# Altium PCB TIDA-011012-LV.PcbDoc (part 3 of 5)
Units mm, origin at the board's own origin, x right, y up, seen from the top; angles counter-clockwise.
Board outline 250 x 280 mm, 4 copper layers (Top Layer, Layer 1, Layer 2, Bottom Layer), stack 2.208 mm thick; 410 components, 230 nets, 1280 pads, 1868 vias.
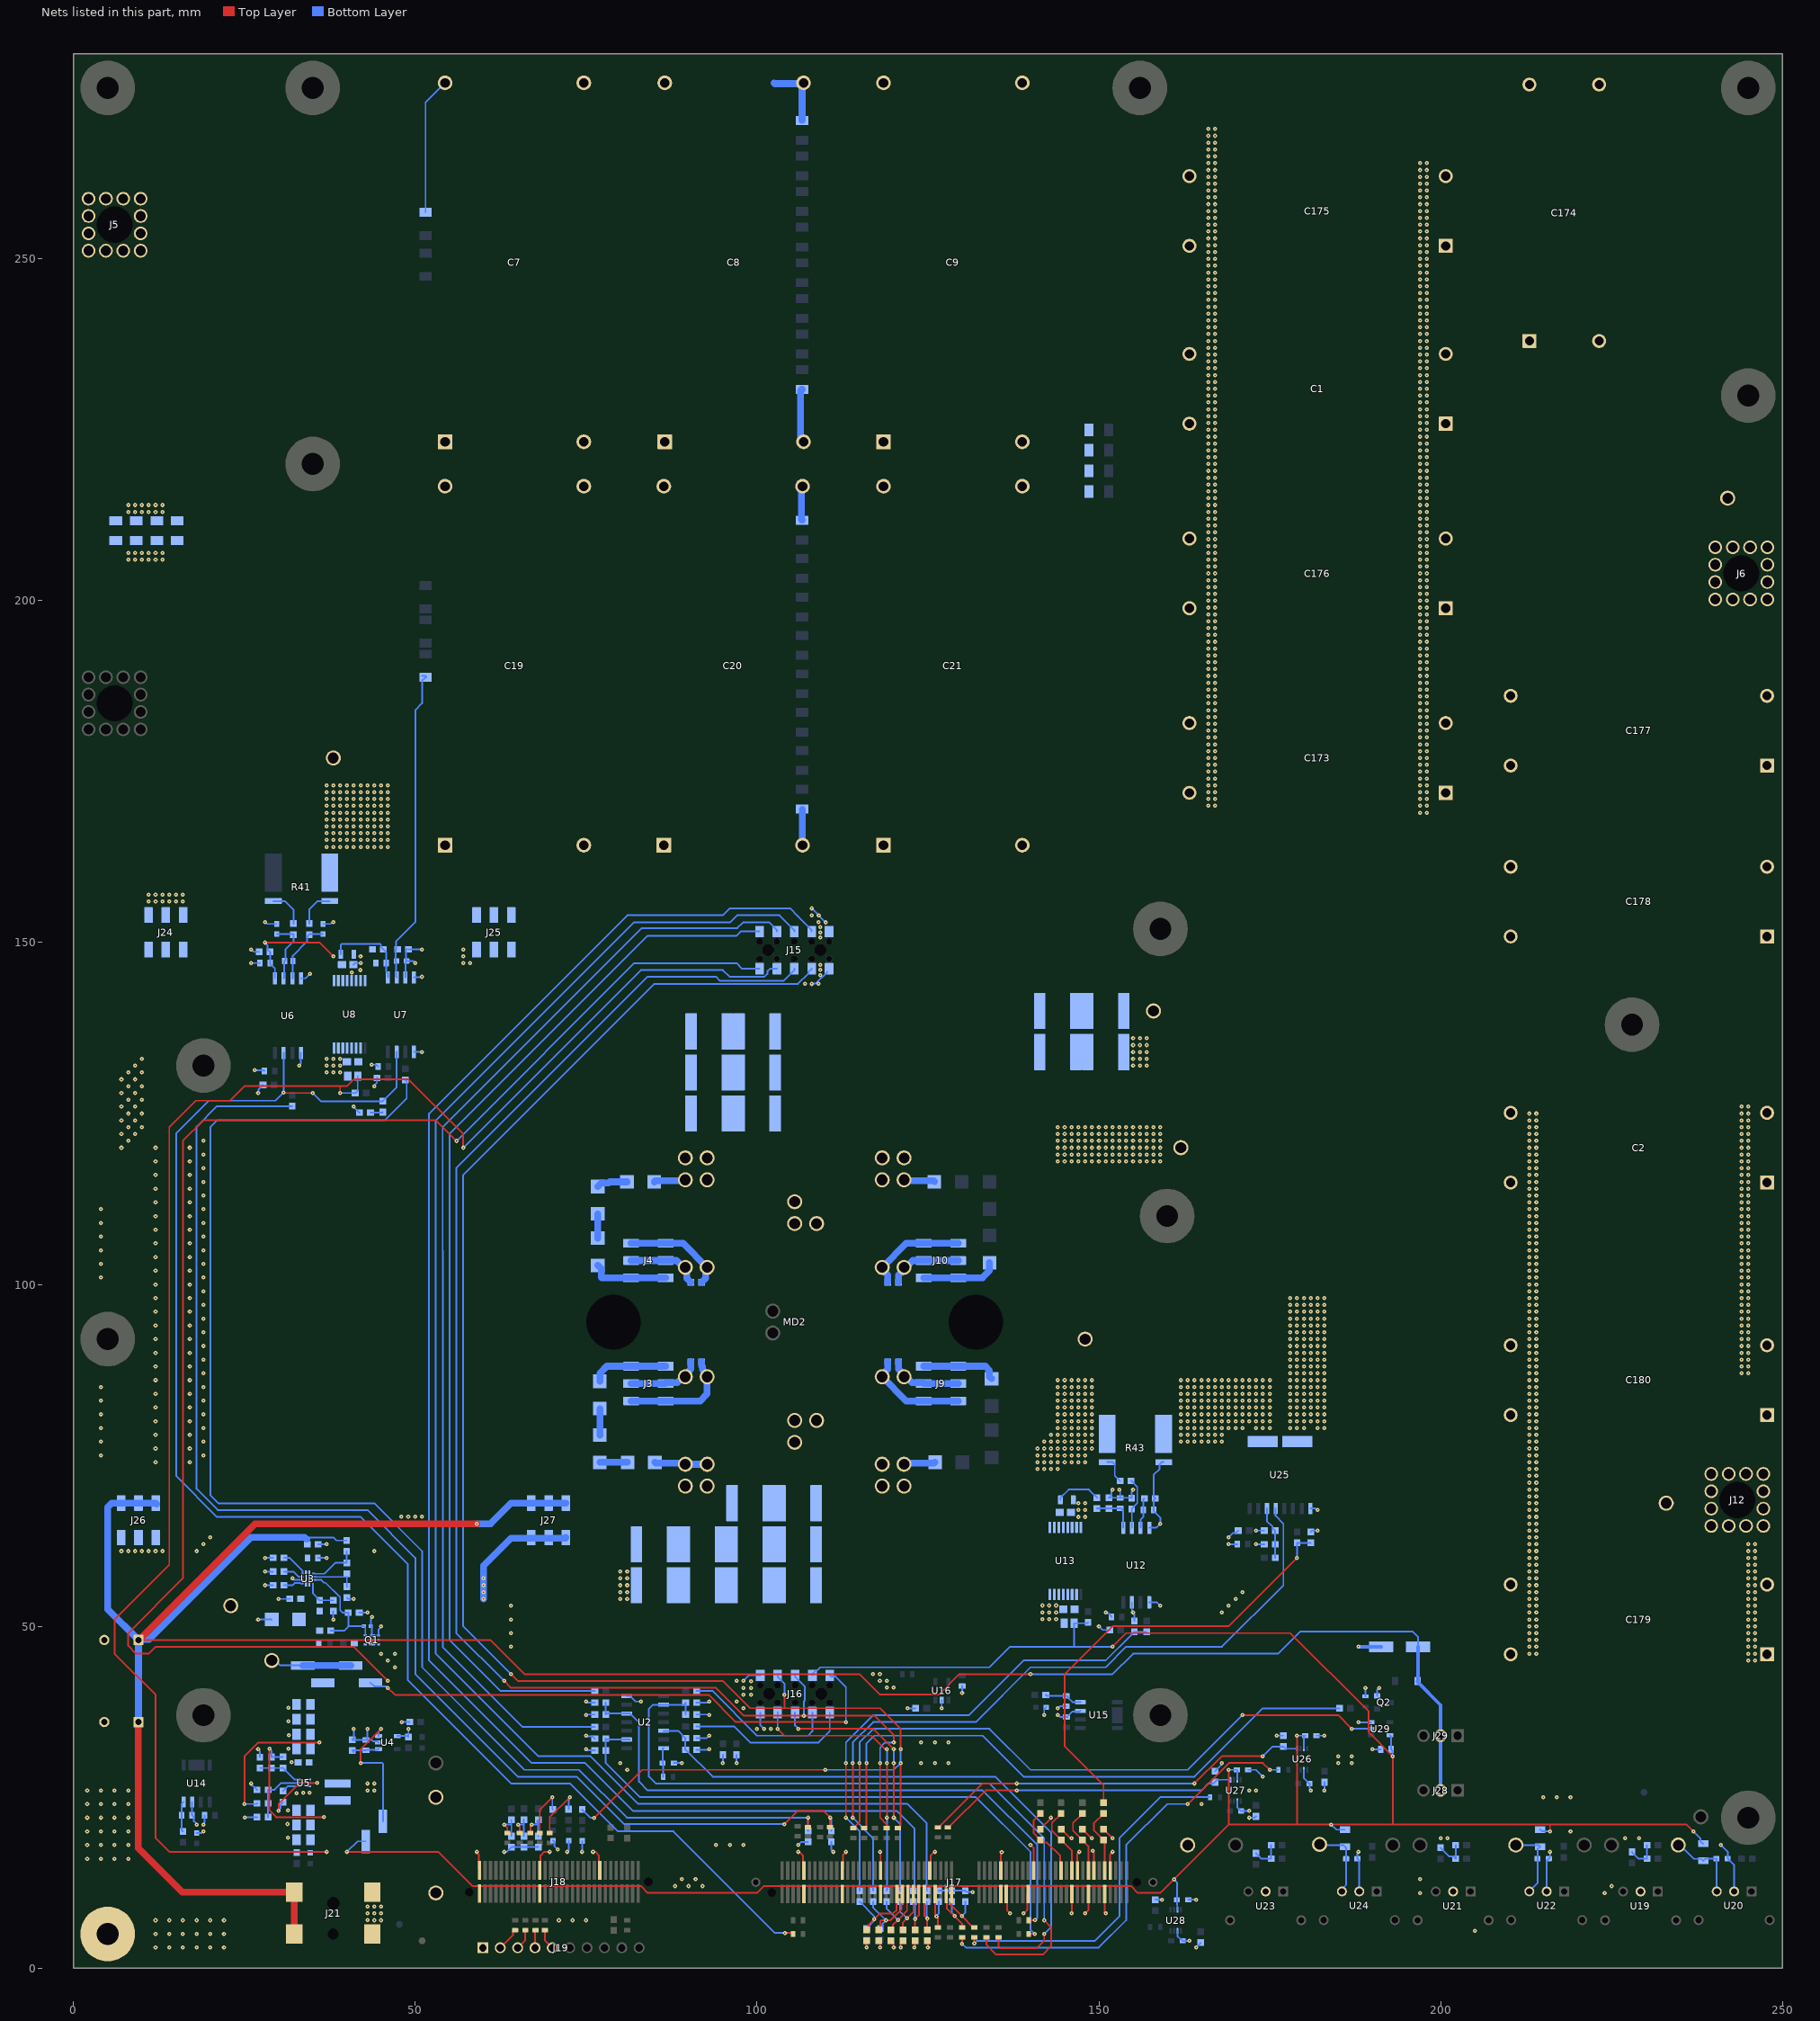
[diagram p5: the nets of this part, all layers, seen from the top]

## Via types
v1: diameter 0.6, hole 0.2, Top Layer to Bottom Layer, tented both sides, 1862 vias
v2: diameter 0.61, hole 0.203, Top Layer to Bottom Layer, tented both sides, 6 vias

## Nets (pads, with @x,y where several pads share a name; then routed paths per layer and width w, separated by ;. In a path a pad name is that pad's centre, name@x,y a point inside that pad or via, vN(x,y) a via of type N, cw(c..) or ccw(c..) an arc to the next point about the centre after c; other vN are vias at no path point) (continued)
5V: C63.1 C67.1 C68.1 C69.1 C88.2 C90.1 C119.2 C121.1 C137.2 C142.2 C144.2 C146.1 D31.2 J15.3 J16.3 J17.48 J17.84 J17.98 J17.112 J18.158 J18.180 J23.1 L1.1 L2.1 L3.1 L7.2 R144.2 R165.2 R185.2 U8.2 U8.3 U13.2 U13.3 U26.7 U27.7 U28.7 U29.5 | length 640.3
  Top Layer w0.25: v1(28.65,32.087) 28.65,23.087 29.65,22.087 v1(36.65,22.087) ; v1(37,17) 14,17 12,19 12,40 6,46 6,51 14,59 14,123 17.875,126.875 22.875,126.875 25,129 39,129 40,129 41,130 ; v1(40,17) 53.362,17 58.362,12 J18.180@59.399,12 ; J18.180@59.399,10.906 J18.180@59.399,12 ; J18.158@68.199,10.906 J18.158@68.199,12 ; J17.112@106.867,10.862 J17.112@106.867,12 ; J17.98@112.467,10.862 J17.98@112.467,12 ; J17.84@118.067,10.862 J17.84@118.067,12 ; J17.48@135.667,10.862 J17.48@135.667,12 ; v1(152,47) 154,49 178,49 189.467,37.533 189.467,34.533 v1(193,31) 193,21 ; v1(169,29) 169,21 ; v1(179,34) 179,21.077 178.923,21 ; v1(216,20) 216,20.96 215.96,21 ; v1(237,20) 236,21 215.96,21 ; J18.180@59.399,12 J18.158@68.199,12 ; J18.158@68.199,12 83,12 84,11 100,11 101,12 101.747,12 101.769,12.022 102.564,12.022 102.586,12 J17.112@106.867,12 ; J17.112@106.867,12 J17.98@112.467,12 ; J17.98@112.467,12 J17.84@118.067,12 ; J17.84@118.067,12 J17.48@135.667,12 ; J17.48@135.667,12 154.675,12 155.675,11 159,11 v1(160.987,12.987) 169,21 ; 169,21 178.923,21 ; 178.923,21 v1(184,21) 193,21 ; 193,21 215.96,21
  Top Layer w0.254: v1(39,128) 39,129 ; 41,130 49,130 57,122 v1(57,120)
  Bottom Layer w0.25: v1(28.65,32.087) 28.98,31.757 R144.2@28.98,30.871 28.996,30.887 C63.1@30.65,30.887 ; v1(39,128) R165.2@41.2,128 ; v1(40,17) 41.54,18.54 J23.1@42.73,18.54 ; R165.2@41.219,128 41.569,128.35 C88.2@41.569,130.453 ; J16.3@108.09,42.82 108.09,43.025 108.6,43.535 108.805,43.535 109.27,44 134,44 137,47 146.5,47 ; R185.2@148.416,50.566 148.296,50.446 C119.2@146.36,50.446 146.372,50.434 146.372,47.128 146.5,47 ; v1(152,47) 146.5,47 ; v1(160.987,12.987) 161.425,12.549 C137.2@161.425,10 161.425,9.244 161.475,9.194 161.475,8.575 U28.7@161.5,8.55 ; v1(169,29) C144.2@170.175,29 170.25,28.925 U27.7@170.25,27.55 ; v1(179,34) C142.2@180.175,34 180,33.825 U26.7@180,32.1 ; v1(184,21) 184.75,20.25 L3.1@186,20.25 ; U29.5@192.574,34.064 192.58,34.064 192.755,33.889 C146.1@192.755,32 192.933,31.822 192.933,31.067 v1(193,31) ; L2.1@214.577,20.28 214.857,20 v1(216,20) ; v1(237,20) 238,19 238,18.572 238.375,18.197 L1.1@238.42,18.197
  Bottom Layer w0.254: v1(57,120) 82.975,145.975 95,145.975 95.975,145 101.098,145 101.502,145.405 101.502,145.788 101.894,146.18 J15.3@102.91,146.18
5V_ISO_DC_SENS: C75.1 C76.1 C84.1 C85.1 C89.2 C91.1 U6.1 U7.1 U8.9 U8.10 U8.11 | length 29.1
  Top Layer w0.25: v1(28,150) 36,150 v1(38,148)
  Bottom Layer w0.25: v1(28,150) 28.37,149.63 28.37,148.999 28.72,148.649 C76.1@28.745,148.649 28.755,148.639 C75.1@28.755,147 ; C75.1@28.755,146.895 29.461,146.189 U6.1@29.461,144.763 ; C89.2@39.108,148.308 39.091,148.324 39.091,149.634 39.26,149.803 44.84,149.803 44.987,149.657 44.987,149.353 45.337,149.003 C85.1@45.338,149.003 ; C85.1@45.363,149.003 45.713,148.653 45.713,148.628 45.755,148.587 C84.1@45.755,147 45.755,145.754 45.996,145.513 U7.1@45.996,144.913
5V_ISO_SN_SENS: C118.2 C120.1 R181.1 U13.9 U13.10 U13.11 | length 6.6
  Bottom Layer w0.25: C118.2@144.373,68.482 144.373,68.782 145.591,70 148.53,70 149.334,69.196 149.359,69.196 149.709,68.846 R181.1@149.709,68.821
12V: J15.1 J16.1 J20.2 | length 296.2
  Top Layer w0.25: v1(46,41) 47.025,39.975 92.909,39.975 96.884,36 v1(113,36) ; v1(46,42) 41,47 12,47 11,46 9.146,46 8,47.146 8,49 16,57 16,121 19,124 53,124 v1(56.01,120.99)
  Bottom Layer w0.25: J20.2@43.46,41.73 43.97,41.22 45.685,41.22 45.905,41 v1(46,41) ; J16.1@110.63,42.82 110.821,42.629 111.494,42.629 113,41.122 v1(113,36)
  Bottom Layer w0.254: v1(56.01,120.99) 82.021,147 97,147 97.82,146.18 J15.1@100.37,146.18
12V_FET_DRAIN: Q1.1 Q1.2 Q1.5 Q1.6 Q1.8 R140.1
12V_IN: C10.1 C55.1 C56.1 C57.1 C122.1 D33.1 J21.1 J21.1A J26.1 J26.3 J26.5 J27.1 J27.3 J27.5 J28.2 J29.2 R134.2 U3.5 | length 416.3
  Top Layer w0.25: C55.1@9.924,48 61,48 66,43 115,43 118,40 126.607,40 129.607,43 v1(140,43)
  Top Layer w1: C56.1@9.45,36 9.45,17.55 15.9,11.1 J21.1A@32.3,11.1 J21.1@32.3,5 ; C55.1@9.924,48.326 26.598,65 v1(59,65)
  Bottom Layer w0.25: 34,63 38,63 38.448,62.552 R134.2@39.963,62.552 ; v1(140,43) 152,43 155,46 176.225,46 179.475,49.25 195.854,49.25 196.7,48.404 C122.1@196.7,47
  Bottom Layer w0.5: C122.1@196.7,47 196.7,42.062 D33.1@196.638,42 196.638,41.847 200,38.485 J29.2@200,34 J28.2@200,26
  Bottom Layer w1: C56.1@9.5,36 C55.1@9.5,48 ; J26.1@12.175,67.884 12.04,68.019 J26.1@12.04,68.025 J26.3@9.5,68.025 J26.5@6.96,68.025 6.935,68 5.586,68 5,67.414 5,52.5 C55.1@9.5,48 ; 34.098,62.725 33.823,63 26,63 11.061,48.061 9.561,48.061 C55.1@9.5,48 ; v1(59,65) 61,65 64,68 72.015,68 J27.1@72.04,68.025
12V_OUT: C59.1 D29.2 D30.1 J20.1 J22.1 R135.2 R139.2 TP1.1 U3.6 | length 11.8
  Bottom Layer w0.25: TP1.1@29,45 29.53,45 30.26,44.27 J22.1@33.539,44.27
  Bottom Layer w1: J22.1@33.539,44.27 J20.1@40.539,44.27
CLK_MOD_DC: R106.1 R154.2 U6.7 U7.7 | length 225.1
  Top Layer w0.25: v1(30.731,128.062) 30.792,128 v1(35,128) ; v1(104.083,5.148) 105.127,5.148 R106.1@105.275,5
  Bottom Layer w0.25: U6.7@30.731,133.863 v1(30.731,128.062) 29.544,126.875 19.8,126.875 15,122.075 15,72 21,66 42.004,66 48.913,59.091 48.913,42.087 64,27 72.629,27 79.622,20.007 87.764,20.007 102.623,5.148 v1(104.083,5.148) ; v1(35,128) 36.2,126.8 R154.2@45.236,126.8 ; R154.2@45.236,126.825 45.611,127.2 45.636,127.2 47.266,128.83 U7.7@47.266,134.013
DATA_I_DC: C78.1 R100.1 R153.2 | length 195.8
  Top Layer w0.25: v1(103.986,21.052) 105.934,23 109.679,23 v1(110.679,22) R100.1@110.679,20.644
  Bottom Layer w0.25: R153.2@32.008,126.075 21,126.075 18,123.075 18,70.083 21.083,67 43,67 50,60 50,43 65,28 73.599,28 80.546,21.052 v1(103.986,21.052) ; v1(110.679,22) 110.867,21.812 C78.1@110.867,20.075
DATA_V_DC: C87.1 R105.1 R163.2 | length 207.3
  Top Layer w0.25: R105.1@107.463,20.644 v1(107.463,22)
  Bottom Layer w0.25: R163.2@48.536,129.928 48.736,129.728 48.736,127.226 45.51,124 21,124 20,123 20,69.186 21.186,68 44,68 51.004,60.996 51.004,43.996 66,29 73.949,29 80.949,22 v1@107.461,22 ; C87.1@107.463,20.075 v1(107.463,22)
DC_BUF_PMW1: J15.2 R112.2 | length 156
  Bottom Layer w0.25: 55,105 55,48 62.464,40.536 67.367,40.536 74.669,40.536 R112.2@76.263,40.536
  Bottom Layer w0.254: 55,105 55,121.979 84.021,151 97,151 97.62,151.62 J15.2@100.37,151.62
DC_BUF_PMW2: J15.4 R111.2 | length 165.1
  Bottom Layer w0.25: 54,105 54.021,104.979 54.021,46.979 65.72,35.28 R111.2@76.263,35.28
  Bottom Layer w0.254: 54,105 54,122.979 83.125,152.104 97.104,152.104 97.942,152.942 101.793,152.942 102.91,151.825 J15.4@102.91,151.62
DC_BUF_PMW3: J16.2 R117.2 | length 23.9
  Bottom Layer w0.25: R117.2@91.15,35.356 96.644,35.356 99,33 109,33 110.63,34.63 J16.2@110.63,37.38
DC_BUF_PMW4: J16.4 R114.2 | length 22.7
  Bottom Layer w0.25: R114.2@91.15,40.549 93.451,40.549 100,34 107.461,34 108.09,34.629 J16.4@108.09,37.38
DC_DAB: C19.1 C20.1 C21.1 C75.2 C76.2 C79.1 C80.1 C84.2 C85.2 C86.1 C89.1 C91.2 C190.1 C191.1 C192.1 C193.1 C194.1 C195.1 C196.1 C197.1 C198.1 C199.1 J25.1 J25.2 J25.3 J25.4 J25.5 J25.6 MD2.DC1- MD2.DC2- R40.1 R41.2 R164.1 TP18.1 U6.4 U7.3 U7.4 U8.12 U8.13 U8.14 U8.15 U8.16 | length 22.9
  Bottom Layer w0.25: v1(26,147) C75.2@27.245,147 ; v1(26,149) 26.351,148.649 C76.2@27.145,148.649 ; v1(28,153) 28.095,153 28.371,152.723 C79.1@29.721,152.723 ; U6.4@33.271,144.763 33.935,144.763 v1(34.591,145.419) ; C80.1@36.507,152.723 37.629,152.723 37.905,153 v1(38,153) ; C91.2@40.926,146.77 41.156,147 v1(42,147) ; U7.3@48.536,144.913 48.593,144.97 48.593,147.143 48.65,147.2 48.65,148.95 R164.1@48.8,149.1 ; C86.1@48.736,147.313 49.687,147.313 v1(50,147) ; R164.1@49,149 v1(51,149) ; U7.4@49.806,144.913 50.913,144.913 v1(51,145)
  Bottom Layer w1: C20.1@106.643,164.257 R40.1@106.643,169.499
  other v1: 80,54 81,54 80,55 81,55 80,56 81,56 80,57 81,57 80,58 81,58 40.7,145.6 41.976,145.988 57,147 58,147 41.991,148 57,148 57,149 37,164 38,164 39,164 40,164 41,164 42,164 42.991,164 43.991,164 44.991,164 45.991,164 37,165 38,165 39,165 40,165 41,165 42,165 42.991,165 43.991,165 44.991,165 45.991,165 37,166 38,166 39,166 40,166 41,166 42,166 42.991,166 43.991,166 44.991,166 45.991,166 37,167 38,167 39,167 40,167 41,167 42,167 42.991,167 43.991,167 44.991,167 45.991,167 37,168 38,168 39,168 40,168 41,168 42,168 42.991,168 43.991,168 44.991,168 45.991,168 37,169 38,169 39,169 40,169 41,169 42,169 42.991,169 43.991,169 44.991,169 45.991,169 37,170 38,170 39,170 40,170 41,170 42,170 42.991,170 43.991,170 44.991,170 45.991,170 37,171 38,171 39,171 40,171 41,171 42,171 42.991,171 43.991,171 44.991,171 45.991,171 37,172 38,172 39,172 40,172 41,172 42,172 42.991,172 43.991,172 44.991,172 45.991,172 37,173 38,173 39,173 40,173 41,173 42,173 42.991,173 43.991,173 44.991,173 45.991,173
DC_DS1: D11.2 J3.1 J3.2 | length 11.2
  Bottom Layer w1: D11.2@77,85.84 77,87 78.04,88.04 J3.1@81.575,88.04 J3.2@86.625,88.04
DC_DS2: D23.2 J9.1 J9.2 | length 11.2
  Bottom Layer w1: J9.1@124.375,88.04 J9.2@129.425,88.04 133.374,88.04 134,87.414 134,86.514 D23.2@134.3,86.214
DC_DS3: D12.2 J4.1 J4.2 | length 11.4
  Bottom Layer w1: D12.2@76.7,102.786 77.2,102.286 77.2,101.046 77.286,100.96 J4.2@81.575,100.96 J4.1@86.625,100.96
DC_DS4: D24.2 J10.1 J10.2 | length 11.2
  Bottom Layer w1: J10.2@124.375,100.96 J10.1@129.425,100.96 132.96,100.96 134,102 D24.2@134,103.16
DC_FAULT_FET1: J15.6 R57.2 | length 235.9
  Bottom Layer w0.25: 119.957,24.057 121.954,24.057 124.825,21.186 R57.2@124.825,11.325
  Bottom Layer w0.254: J15.6@105.45,151.62 105.45,151.825 103.275,154 97.104,154 96.058,152.954 81.975,152.954 53,123.979 53,46 68,31 75.625,31 82.569,24.057 119.957,24.057
DC_FAULT_FET2: J15.8 R68.2 | length 240.3
  Bottom Layer w0.25: 119.316,23 120.444,23 123.006,20.437 123.006,11.47 R68.2@122.862,11.325
  Bottom Layer w0.254: J15.8@107.99,151.62 107.99,151.825 105.992,153.823 105.992,153.851 104.843,155 96,155 95,154 81,154 52,125 52,45 67,30 74.83,30 81.83,23 119.316,23
DC_FAULT_FET3: J16.6 R78.2 | length 38.9
  Top Layer w0.25: v1(106,35) 117,35 v1(120,32) ; v1(120,22) v1(120,30)
  Bottom Layer w0.25: J16.6@105.55,37.38 105.55,35.505 106,35.055 v1(106,35) ; v1(120,22) 120.899,21.101 R78.2@120.899,11.325 ; v1(120,30) v1(120,32)
DC_FAULT_FET4: J16.8 R86.2 | length 40.3
  Top Layer w0.25: v1(103,35) 104,34 116.718,34 118.651,32.067 118.933,32.067 v1(119,32) ; v1(119,22) v1(119,30)
  Bottom Layer w0.25: v1(103,35) 103,37.37 J16.8@103.01,37.38 ; R86.2@118.936,11.325 119,11.389 v1(119,22) ; v1(119,30) v1(119,32)
DC_G1: J3.5 J3.6 MD2.G1 R19.2 | length 16.6
  Bottom Layer w1: J3.5@81.575,82.96 J3.6@86.625,82.96 91.66,82.96 92.7,84 MD2.G1@92.7,86.5 92.7,86.825 92,87.525 92,88 91.9,88.1 R19.2@91.9,88.7
DC_G2: J9.5 J9.6 MD2.G2 R29.2 | length 15.1
  Bottom Layer w1: R29.2@119.1,88.7 119.1,87.625 118.3,86.825 MD2.G2@118.3,86.5 121.84,82.96 J9.5@124.375,82.96 J9.6@129.425,82.96
DC_G3: J4.5 J4.6 MD2.G3 R20.2 | length 15.1
  Bottom Layer w1: J4.6@81.575,106.04 J4.5@86.625,106.04 89.16,106.04 MD2.G3@92.7,102.5 92.47,102.27 92.47,100.87 R20.2@91.9,100.3
DC_G4: J10.5 J10.6 MD2.G4 R30.2 | length 15.1
  Bottom Layer w1: R30.2@119.1,100.3 119.1,101.375 118.3,102.175 MD2.G4@118.3,102.5 121.84,106.04 J10.6@124.375,106.04 J10.5@129.425,106.04
DC_GD_RDY: J15.7 J16.7 R50.2 R82.1 | length 270.3
  Top Layer w0.25: v1(64,43) 65,42 95,42 98.98,38.02 104,38.02 104.106,38.02 ; v1(76.149,21.972) 83.177,29 v1(110,29) ; v1(104,40) 104,38.126 104.106,38.02 ; R82.1@120.594,20.494 120.719,20.494 120.919,20.694 120.919,20.819 121,20.9 v1(121,30) ; v1(121,32) 121,35 117.98,38.02 104.106,38.02
  Bottom Layer w0.25: 57,103 57,50 v1(64,43) ; R50.2@74.411,23.205 74.411,23.18 74.761,22.83 74.786,22.83 75.644,21.972 v1(76.149,21.972) ; J16.7@103.01,42.82 103.01,42.615 104,41.625 v1(104,40) ; v1(110,29) 120,29 v1(121,30) v1(121,32)
  Bottom Layer w0.254: 57,103 57,116 84.95,143.95 105.992,143.95 107.482,145.441 107.482,145.672 J15.7@107.99,146.18
DC_GD_RST/EN: J15.5 J16.5 R83.1 | length 222.5
  Top Layer w0.25: v1(63,42) 64,41 94,41 98.087,36.913 v1(106.847,36.913) 117.209,36.913 120,34.122 v1(120,33) ; v1(118,30) 118,22 118.948,21.052 R83.1@118.948,20.494
  Bottom Layer w0.25: 56,107 56,49 v1(63,42) ; J16.5@105.55,42.82 105.55,42.615 107,41.165 107,39.163 106.847,39.01 v1(106.847,36.913) ; v1(118,30) 118,32.253 118.747,33 v1(120,33)
  Bottom Layer w0.254: 56,107 56,117 84,145 94,145 94.596,144.404 103.879,144.404 105.45,145.975 J15.5@105.45,146.18
DC_KS1: J3.3 J3.4 MD2.KS1 R19.1 | length 10.9
  Bottom Layer w1: J3.3@81.575,85.5 J3.4@86.625,85.5 86.76,85.635 88.31,85.635 89.175,86.5 MD2.KS1@89.5,86.5 89.5,86.825 90.3,87.625 R19.1@90.3,88.7
DC_KS2: J9.3 J9.4 MD2.KS2 R29.1 | length 10.9
  Bottom Layer w1: R29.1@120.7,88.7 120.7,87.625 121.5,86.825 MD2.KS2@121.5,86.5 121.825,86.5 122.69,85.635 124.24,85.635 J9.3@124.375,85.5 J9.4@129.425,85.5
DC_KS3: J4.3 J4.4 MD2.KS3 R20.1 | length 10.9
  Bottom Layer w1: J4.4@81.575,103.5 J4.3@86.625,103.5 88.175,103.5 89.175,102.5 MD2.KS3@89.5,102.5 89.73,102.27 89.73,100.87 R20.1@90.3,100.3
DC_KS4: J10.3 J10.4 MD2.KS4 R30.1 | length 10.9
  Bottom Layer w1: R30.1@120.7,100.3 120.7,101.375 121.5,102.175 MD2.KS4@121.5,102.5 121.825,102.5 122.825,103.5 J10.4@124.375,103.5 J10.3@129.425,103.5
DC_OC: R94.2 U25.7 | length 107.2
  Top Layer w0.25: v1(114,22) v1(114,30)
  Bottom Layer w0.25: v1(114,22) 116.973,19.027 R94.2@116.973,11.325 ; v1(114,30) 114,33 117,36 132,36 140,44 151,44 154,47 168,47 177,56 177,65 175.865,66.135 U25.7@175.865,67.247
DC_OC_CMP: C116.1 R109.2 R183.2 | length 73.2
  Top Layer w0.25: v1(113,22) v1(113,30)
  Bottom Layer w0.25: v1(113,22) 115.01,19.99 R109.2@115.01,11.325 ; v1(113,30) 113,33 117,37 131,37 139,45 150.984,45 154.809,48.825 154.834,48.825 155.184,49.175 C116.1@155.184,49.2 R183.2@157,49.2
DC_POS: C7.2 C8.2 C9.2 C11.2 C12.2 C13.2 C23.2 C24.2 C25.2 C65.2 C71.2 C163.2 C164.2 D3.1 D4.1 J5.1 J24.1 J24.2 J24.3 J24.4 J24.5 J24.6 MD2.DC1+ MD2.DC2+ R3.2 R158.1 TP14.1 | length 41.7
  Bottom Layer w0.254: R158.1@51.5,256.809 51.5,272.9 C7.2@54.35,275.75
  Bottom Layer w1: D4.1@84.957,115 85.107,115.15 89.35,115.15 MD2.DC2+@89.5,115.3 ; D3.1@85.057,73.977 85.195,73.838 89.362,73.838 MD2.DC1+@89.5,73.7 MD2.DC1+@92.7,73.7 ; 102.5,275.75 102.621,275.629 106.006,275.629 106.592,275.043 R3.2@106.592,270.25
  other v1: 155,132 156,132 157,132 155,133 156,133 157,133 155,134 156,134 157,134 155,135 156,135 157,135 155,136 156,136 157,136 11,156 12,156 13,156 14,156 15,156 16,156 11,157 12,157 13,157 14,157 15,157 16,157
DC_PWM1: C49.2 R59.2 R120.2 U2.5 | length 90
  Top Layer w0.25: R59.2@139.725,7 139.748,7.023 v1(140.658,7.023)
  Bottom Layer w0.25: C49.2@77.863,38.818 R120.2@77.863,37.099 78.015,37.251 81.4,37.251 82.729,35.922 82.729,27.271 84,26 133,26 141,18 141,7.365 v1(140.658,7.023)
DC_PWM2: C50.2 R61.2 R121.2 U2.2 | length 87.7
  Top Layer w0.25: R61.2@139.725,5 139.736,5.011 v1(140.617,5.011)
  Bottom Layer w0.25: C50.2@77.863,33.441 R121.2@77.863,31.842 77.863,30 82.863,25 132,25 140,17 140,5.627 v1(140.617,5.011) ; C50.2@77.863,33.562 77.983,33.441 U2.2@80.925,33.441 U2.2@81.4,33.441
DC_PWM3: C52.2 R63.2 R123.2 U2.12 | length 88.7
  Top Layer w0.25: R63.2@135.315,4.496 135.315,3.234 135.611,2.938 140.938,2.938 142,4 v1(142,5)
  Bottom Layer w0.25: U2.12@86.325,34.711 88.452,34.711 89.525,33.638 C52.2@89.55,33.638 89.475,33.563 89.475,31.924 R123.2@89.55,31.924 89.575,31.924 93.499,28 134.862,28 143,19.862 143,6 v1(142,5)
DC_PWM4: C51.2 R66.2 R122.2 U2.9 | length 106.7
  Top Layer w0.25: R66.2@133.539,4.496 133.539,3.455 134.995,2 141.78,2 143,3.22 143,6 v1(142,7)
  Bottom Layer w0.25: R122.2@89.55,37.099 C51.2@89.55,38.818 89.253,38.521 U2.9@86.325,38.521 84.778,38.521 84.178,37.921 84.178,27.996 85.174,27 134,27 142,19 v1(142,7)
DEBUG_GPIO1: J19.5 R126.1 | length 3
  Top Layer w0.254: R126.1@68.952,5.55 68.952,4.074 J19.5@70.049,2.976
DEBUG_GPIO2: J19.4 R128.1 | length 2.6
  Top Layer w0.254: J19.4@67.509,2.976 67.509,5.46 R128.1@67.599,5.55
DEBUG_GPIO3: J19.3 R130.1 | length 3
  Top Layer w0.254: J19.3@64.969,2.976 66.096,4.103 R130.1@66.096,5.55
DEBUG_GPIO4: J19.2 R132.1 | length 3.5
  Top Layer w0.254: J19.2@62.429,2.976 64.297,4.844 64.297,5.352 64.495,5.55 R132.1@64.599,5.55
EF_dVdt: C61.1 U3.7 | length 2.9
  Bottom Layer w0.25: C61.1@30.8,56 32,56 32.325,56.325 33.2,56.325 33.274,56.251 U3.7@33.499,56.251
EF_EN: R134.1 R138.2 U3.1 | length 7.3
  Bottom Layer w0.25: U3.1@35,57.7 35.004,57.696 35.279,57.696 35.3,57.675 36.675,57.675 38.278,59.278 R138.2@39.983,59.278 39.963,59.298 R134.1@39.963,60.952
EF_ILIM: R136.2 U3.9 | length 2.9
  Bottom Layer w0.25: R136.2@30.8,58 32.17,58 32.945,57.225 33.235,57.225 U3.9@33.35,57.225
EF_ITIMER: C60.1 U3.10 | length 3.9
  Bottom Layer w0.25: C60.1@30.8,60 31.627,60 33.5,58.127 U3.10@33.5,57.7
EF_OVLO: R138.1 R141.2 U3.2 | length 6.3
  Bottom Layer w0.25: U3.2@35.15,57.225 40.025,57.225 R138.1@40.053,57.198 ; R138.1@39.983,57.221 39.983,55.817 R141.2@40,55.8
EF_PG: C62.1 Q1.3 R139.1 R142.2 U3.3 | length 16.8
  Bottom Layer w0.25: U3.3@35.15,56.775 36.256,56.775 36.256,56.744 36.628,56.372 36.863,56.372 39,54.235 39,52.325 39.325,52 R142.2@40.2,52 40.238,51.962 40.238,50 42.55,50 42.687,49.863 42.687,48.689 42.678,48.679 Q1.3@42.678,48.664 ; R139.1@37.61,49.356 39.624,49.356 40.268,50
EF_PGTH: R135.1 R137.2 U3.4 | length 4.9
  Bottom Layer w0.25: U3.4@35,56.25 35,55 35,54.825 36,53.825 R135.1@36,53.8 R137.2@38,53.8
FAN_EN: R88.1 R187.1 | length 88.9
  Top Layer w0.25: R88.1@115.651,20.494 115.776,20.494 115.976,20.694 115.976,20.819 116,20.843 v1(116,30)
  Bottom Layer w0.25: v1(116,30) 116,32.884 117.116,34 133,34 139,28 164,28 174,38 R187.1@185.2,38
FAN_PWM: R90.1 U29.2 | length 95.2
  Top Layer w0.25: R90.1@114.092,20.494 115,21.402 v1(115,30) ; v1(171,37) 185,37 v1(187,35)
  Bottom Layer w0.25: v1(115,30) 115,33 117,35 134,35 140,29 163,29 v1(171,37) ; v1(187,35) 187.007,35.007 189.817,35.007 U29.2@189.824,35.014
FSIRXA_CLK: R71.2 R215.1 | length 65.5
  Top Layer w0.25: v1(129.988,3.563) R71.2@129.988,4.496 ; v1(163,24) 163.034,24 169.034,30 174,30 v1(175,29)
  Bottom Layer w0.25: v1(129.988,3.563) 130.56,2.99 131.506,2.99 131.519,2.978 132.036,2.978 132.049,2.99 149.99,2.99 154,7 154,18 160,24 v1(163,24) ; v1(175,29) R215.1@176.275,29
FSIRXA_D0: R69.2 R216.1 | length 51
  Top Layer w0.25: R69.2@131.764,4.496 131.778,4.482 v1(131.778,3.603)
  Bottom Layer w0.25: v1(131.778,3.603) 132.175,4 137.568,4 140.21,4 149.427,4 153,7.573 153,19 159,25 R216.1@166.275,25
FSITXA_CLK: C147.1 R72.1 U26.5 | length 57.6
  Top Layer w0.25: R72.1@126.444,20.583 126.569,20.583 132.987,27 v1(138,27) ; v1(164,27) 168,31 v1(174,31)
  Bottom Layer w0.25: v1(138,27) v1(164,27) ; v1(174,31) 175.4,32.4 C147.1@177,32.4 177.3,32.1 U26.5@179,32.1
FSITXA_D0: C149.1 R70.1 U27.5 | length 44.2
  Top Layer w0.25: R70.1@127.888,20.583 128.013,20.583 133.43,26 v1(138,26)
  Bottom Layer w0.25: v1(138,26) 165,26 166,27 166.8,27 C149.1@167,27.2 167.35,27.55 U27.5@169.25,27.55
GND: C10.2 C22.2 C27.2 C29.2 C30.2 C33.2 C34.2 C35.2 C40.2 C41.2 C43.2 C45.1 C46.2 C49.1 C50.1 C51.1 C52.1 C53.1 C55.2 C56.2 C57.2 C59.2 C60.2 C61.2 C62.2 C64.2 C66.2 C67.2 C68.2 C69.2 C70.2 C72.2 C73.2 C74.2 C78.2 C81.2 C82.2 C83.2 C87.2 C88.1 C90.2 C113.2 C114.2 C116.2 C119.1 C121.2 C122.2 C123.2 C124.1 C125.2 C126.2 C127.1 C128.2 C129.2 C135.1 C137.1 C138.1 C140.1 C141.1 C142.1 C143.1 C144.1 C145.1 C146.2 C147.2 C148.2 C149.2 C150.2 C151.2 C152.2 C153.2 C154.2 C155.2 C158.1 C159.2 C160.2 C162.2 C169.2 C170.2 C171.1 C172.2 D25.1 D26.1 D27.1 D30.2 H11.1 J15.9 J15.10 J16.9 J16.10 J17.7 J17.10 J17.13 J17.16 J17.19 J17.22 J17.35 J17.38 J17.46 J17.47 J17.65 J17.83 J17.97 J17.111 J18.135 J18.157 J18.179 J19.1 J21.2 J21.3 J26.2 J26.4 J26.6 J27.2 J27.4 J27.6 Q1.4 Q1.7 Q2.2 R53.1 R54.1 R55.1 R120.1 R121.1 R122.1 R123.1 R136.1 R137.1 R141.1 R142.1 R145.2 R146.1 R147.1 R148.1 R188.1 R190.1 R200.1 R201.1 R203.2 R205.1 R206.1 R207.1 TP2.1 TP21.1 TP22.1 TP23.1 U2.7 U3.8 U4.2 U4.4 U5.3 U6.5 U7.5 U8.4 U8.5 U8.6 U8.7 U8.8 U12.5 U12.7 U13.4 U13.5 U13.6 U13.7 U13.8 U14.3 U15.3 U16.2 U19.2 U20.2 U21.2 U22.2 U23.2 U24.2 U25.3 U26.2 U27.2 U28.2 U29.3 | length 260.7
  Top Layer w0.25: v1(76,17) 76.338,17 76.874,16.464 76.874,14.431 J18.135@76.999,14.306 ; v1(106,17) 106.162,17 106.742,16.42 106.742,14.387 J17.111@106.867,14.262 ; J17.97@112.467,14.262 112.592,14.387 112.592,16.592 v1(113,17) ; v1(116,3) 116.011,3.011 C46.2@116.011,3.983 ; C43.2@117.787,3.983 118,3.77 v1(118,3) ; v1(118,17) 118.067,16.933 J17.83@118.067,14.262 ; C41.2@119.562,3.983 119.912,3.633 119.912,3.182 120,3.095 v1(120,3) ; v1(121,3) 121,3.645 C35.2@121.338,3.983 ; v1(123,3) 123.114,3.114 C33.2@123.114,3.983 ; C30.2@124.89,3.983 125,3.873 v1(125,3) ; J17.65@125.267,14.262 125.392,14.387 125.392,16.42 125.971,17 v1(126,17) ; J17.47@135.667,14.262 135.667,16.827 v1(135.79,16.95) ; J17.46@136.467,10.862 136.592,10.737 136.592,8.408 v1(137,8) ; v1(139,8) 139.542,8.542 139.542,10.737 J17.38@139.667,10.862 ; v1(140,18) 140.467,17.533 J17.35@140.467,14.262 ; C40.2@141.442,20.339 141.442,20.364 143,21.923 v1(143,22) ; C34.2@144.492,20.339 144.492,20.314 145.806,19 v1(146,19) ; v1(146,8) 146.067,8.067 J17.22@146.067,10.862 ; J17.19@146.867,14.262 146.867,16.754 v1(147.113,17) ; C29.2@147.592,20.339 147.592,20.314 148.906,19 v1(149,19) ; v1(148,8) 148.467,8.467 J17.16@148.467,10.862 ; v1(149.094,17.139) 149.094,17.044 149.267,16.871 J17.13@149.267,14.262 ; C27.2@150.692,20.339 150.692,20.314 152,19.006 v1(152,19) ; J17.10@150.867,10.862 150.867,8.133 v1(151,8) ; J17.7@151.667,14.262 151.667,16.667 v1(152,17)
  Top Layer w0.254: v1(59,17) 59,16.906 59.276,16.631 59.276,14.429 J18.179@59.399,14.306 ; J18.157@68.199,14.306 68.322,14.429 68.322,16.465 68.856,17 v1(69.656,17)
  Bottom Layer w0.25: U14.3@17.365,24.3 17.349,24.284 C125.2@17.349,22.357 17.616,22.09 17.616,21.482 18,21.097 v2(18,21) ; C124.1@18,19.75 18.692,19.75 18.942,20 v2(19,20) ; v2(19,21) 19,21.095 19.15,21.245 C123.2@19.15,22.357 ; v2@25,22 25.087,22.087 R145.2@26.85,22.087 ; v1(26,27) 26,26.912 26.825,26.087 C172.2@26.85,26.087 ; v1(26.482,131.334) 27.803,131.334 C73.2@27.905,131.232 ; v1(27,32) 27.271,31.729 R146.1@27.271,30.86 ; v1(27,51) D30.2@29,51 ; v1(27,128) 27.067,128.067 27.067,128.546 27.695,129.175 C74.2@27.72,129.175 ; v1(28,56) C61.2@29.2,56 ; v1(28,58) R136.1@29.2,58 ; v1(28,60) C60.2@29.2,60 ; v1(30,54) 31.629,54 C59.2@31.649,54.019 ; v1(32,57) 32.225,56.775 U3.8@33.35,56.775 ; v1(33,132) 33,132.095 33.271,132.366 U6.5@33.271,133.863 ; C10.2@35.755,60 v1(37,60) ; C57.2@35.8,62 v1(37,62) ; v1(38,51) R137.1@38,52.2 ; R141.1@40,54.2 40.2,54 v1(41,54) ; v1(41,35) 41,33.625 C64.2@40.781,33.406 40.826,33.361 C22.2@42.781,33.361 43.656,33.361 43.843,33.175 44.45,33.175 U4.2@44.625,33 ; v1(41,126) 41,125.941 41.816,125.125 C81.2@41.841,125.125 ; R142.1@41.8,52 v1(43,52) ; C22.2@43,33.485 v1(43,35) ; v1(43.625,132.141) 44.288,132.141 C82.2@44.544,131.885 ; v1(43.675,51.37) 43.675,51.275 43.5,51.1 C62.2@43.5,50 43.624,49.876 43.624,48.689 43.649,48.664 Q1.4@44.628,48.664 44.628,49.533 45,49.905 v1(45,50) ; v1(44,129) 44,129.095 44.4,129.495 44.4,130.198 C83.2@44.408,130.206 ; U4.4@47.375,33.95 48.85,33.95 C66.2@49,33.8 v1(49,35) ; v1(48,36) R148.1@49.2,36 ; U7.5@49.806,134.013 50.987,134.013 v1(51,134) ; v1(75,32) 75.158,31.842 R121.1@76.263,31.842 ; v1(75,34) 75.088,33.912 75.913,33.912 C50.1@76.263,33.562 ; v1(75,37) 75.099,37.099 R120.1@76.263,37.099 ; v1(75,39) 75.182,38.818 C49.1@76.263,38.818 ; U2.7@80.925,39.791 81.4,39.791 82.191,39 v1(83,39) ; C45.1@87.825,30 v1(89,30) ; R123.1@91.15,31.924 92.924,31.924 v1(93,32) ; C52.1@91.15,33.638 92.638,33.638 v1(93,34) ; R122.1@91.15,37.099 92.901,37.099 v1(93,37) ; C51.1@91.15,38.818 92.818,38.818 v1(93,39) ; v1(95,30) C53.1@95,31.2 ; v1(97,30) R205.1@97,31.2 ; v1(98,42) 98.82,42.82 J16.9@100.47,42.82 ; J16.10@100.47,37.38 100.47,35.53 v1(101,35) ; v1(106,18) 106.055,18 106.505,18.45 107.438,18.45 C87.2@107.463,18.475 ; v1(108,143.95) 108.077,144.027 108.582,144.027 J15.9@110.276,145.721 ; v1(108,155) v1(110.046,152.954) ; C78.2@110.867,18.475 110.867,17.287 v1(111.154,17) ; v1(122,38) R190.1@123.2,38 ; C155.2@126.569,11.325 C154.2@128.5,11.325 C153.2@130.463,11.325 130.651,11.137 v1(131.567,11.137) ; v1(127,38) 127.01,38.01 127.01,39.167 U16.2@127.02,39.177 ; v1(130,40.25) C129.2@130,41.245 ; v1(142,37) 142,37.842 142.04,37.882 142.04,37.907 142.29,38.157 C127.1@142.315,38.157 ; v1(144,37) 144.095,37 144.34,36.755 145.372,36.755 146.15,37.533 147.198,37.533 U15.3@147.3,37.635 ; v1(144,38) 144.036,38 144.338,38.302 C128.2@145.213,38.302 ; v1(150,50) 150.541,49.459 C114.2@151.607,49.459 ; v1(151,52) 151.067,51.933 151.389,51.933 151.868,51.454 C113.2@151.868,51.349 ; U12.7@154.83,53.5 154.83,52.265 155,52.095 v1(155,52) 155,51.905 155.184,51.721 C116.2@155.184,50.8 ; U12.5@157.37,53.5 158.5,53.5 v1(159,53) ; C151.2@158.25,10 v1(159.25,10) ; U28.2@161.5,5.45 161.5,4.675 161.919,4.256 161.994,4.256 C145.1@162.25,4 v1(163.25,4) ; C137.1@163.075,10 v1(164.25,10) ; v1(164.25,3) 164.25,3.056 164.891,3.697 C152.2@164.891,3.722 ; C149.2@167,28.8 167,28.825 167.933,29.758 167.933,29.933 v1(168,30) ; v1(169,62) C158.1@170.245,62 ; v1(169,63) 169.65,63.65 170.043,63.65 C159.2@170.393,64 ; U27.2@170.25,24.45 170.25,23.512 170.762,23 C143.1@170.825,23 v1(172,23) ; C144.1@171.825,29 173,29 v1(174,28) ; v1(172,22) 172.8,22 C150.2@173,22.2 ; v1(173,62) R203.2@174.2,62 ; v1(173,64) C162.2@174.2,64 ; v1(176,34) C147.2@177,34 ; U26.2@180,29 180,27.762 180.762,27 C141.1@180.825,27 180.825,26.269 181,26.095 v1(181,26) ; U25.3@180.945,67.247 181.658,67.247 181.905,67 v1(182,67) ; C160.2@181,63.8 181.2,64 v1(182,64) ; C142.1@181.825,34 v1(183,34) ; v1(183,26) C148.2@183,27.2 ; C140.1@187.825,16 187.825,16.825 v1(188,17) ; C140.1@187.842,16 188.098,15.744 188.098,11.229 U24.2@188.101,11.226 ; v1(188,36) 188.036,35.964 U29.3@189.824,35.964 ; R188.1@189,39.75 v1(189,41) ; v1(190,32) C146.2@191.245,32 ; Q2.2@190.704,39.8 190.704,40.704 v1(191,41) ; U22.2@215.52,11.226 215.52,15.744 215.776,16 C138.1@215.825,16 216,16.175 v1(216,17) ; v1(241,18) 242,17 C135.1@242,16 ; C135.1@242.064,16 242.939,15.125 U20.2@242.939,11.226
  Bottom Layer w0.254: v1(63,17) 63.384,17 64.066,17.682 R53.1@64.066,17.707 R55.1@68,17.707 ; D25.1@70.163,18.652 70.325,18.489 70.325,17.871 v1(70.808,17.387) ; v1(72.199,17) 72.268,17 72.428,17.161 D26.1@72.428,18.643 ; v1(74.411,17) 74.412,17.002 D27.1@74.412,18.607
  Bottom Layer w0.5: v1(188,47) C122.2@191.3,47
  Bottom Layer w1: v1(60,54) 60,58.883 64,62.883 71.948,62.883 J27.2@72.04,62.975
  other v1: 12,3 14,3 16,3 18,3 20,3 22,3 12,5 14,5 16,5 18,5 20,5 22,5 205.007,5.466 12,7 14,7 16,7 18,7 20,7 22,7 43.012,7.019 44.001,7 45.003,7 71,7 73,7 75,7 44.001,8 45.003,8 43.012,8.019 43.012,8.999 44.001,8.98 45.003,8.98 197,11 224,11 88,12 90,12 92,12 225,12 89,13 91,13 197,13 2,16 4,16 6,16 8,16 2,18 4,18 6,18 8,18 94,18 96,18 98,18 200,19 201,19 227,19 229,19 31.367,19.09 2,20 4,20 6,20 8,20 219,20 31.312,21.078 2,22 4,22 6,22 8,22 31.363,23.079 2,24 4,24 6,24 8,24 165,24 215,25 217,25 219,25 32.646,25.559 33.592,25.623 34.542,25.628 2,26 4,26 6,26 8,26 43,26 44,26 172,26 173,26 43,27 44,27 81,29 80,30 124,30 126,30 128,30 185,30 187,30 31.911,30.126 185,31 187,31 31.43,32.096 124,33 126,33 128,33 31.486,34.087 100,35 102,35 31.43,36.088 98,38 31.425,38.104 97,39 99.1,39.962 98,40 98,41 99.1,40.982 118.966,41.039 119.966,41.039 99.1,41.989 97,42 117.966,42.039 118.966,42.039 116.966,43.039 117.966,43.039 47,44 46,45 45,46 47,46 64,47 64,49 64,51 141.749,51.044 142.749,51.044 143.749,51.044 168,52 141.749,52.044 142.749,52.044 143.749,52.044 64,53 169,53 141.749,53.044 142.749,53.044 143.749,53.044 170,54 60,55 171,55 60,56 60,57 7,61 8,61 9,61 10,61 11,61 12,61 13,61 18,61 44,61 19,62 20,63 47.966,66.039 48.966,66.039 49.966,66.039 50.966,66.039 12,74 17,74 4,75 19,75 12,76 17,76 4,77 19,77 12,78 17,78 4,79 19,79 12,80 17,80 4,81 19,81 12,82 17,82 4,83 19,83 12,84 17,84 4,85 19,85 12,86 17,86 19,87 12,88 17,88 19,89 12,90 17,90 19,91 12,92 17,92 19,93 12,94 17,94 19,95 12,96 17,96 19,97 12,98 17,98 19,99 12,100 17,100 4,101 19,101 12,102 17,102 4,103 19,103 12,104 17,104 4,105 19,105 12,106 17,106 4,107 19,107 12,108 17,108 4,109 19,109 12,110 17,110 4,111 19,111 12,112 17,112 19,113 12,114 17,114 19,115 12,116 17,116 19,117 12,118 17,118 19,119 7,120 12,120 17,120 8,121 19,121 7,122 9,122 8,123 10,123 7,124 9,124 8,125 10,125 7,126 9,126 8,127 10,127 7,128 9,128 8,129 10,129 7,130 9,130 8,131 10,131 37,131 38,131 39,131 9,132 37,132 38,132 39,132 10,133 37,133 38,133 39,133 107,144 109,144 109.242,145.24 109.25,146 109.25,146.75 109.25,150.75 109.244,151.505 109.25,152.25 109,153 109.023,153.977 108,154 8,206 9,206 10,206 11,206 12,206 13,206 8,207 9,207 10,207 11,207 12,207 13,207
  other v2: 25.044,22.044
I_DC_MINUS: R41.4 R152.1 | length 5.6
  Bottom Layer w0.25: R152.1@34.49,152.773 34.49,154.863 35.695,156.068 R41.4@37.481,156.068
I_DC_POS: R41.3 R151.1 | length 5.5
  Bottom Layer w0.25: R41.3@29.231,156.068 30.932,156.068 32.173,154.827 R151.1@32.173,152.773
I_HALL: C160.1 R44.1 R199.2 | length 66.4
  Top Layer w0.254: R44.1@150.688,24.209 150.688,26.748 145,32.436 145,43 152,50 169,50 v1(179,60)
  Bottom Layer w0.25: v1(179,60) R199.2@179,62.2 C160.1@181,62.2
I_HALL_N: R43.2 U25.1
  other v1: 162,77 163,77 164,77 165,77 166,77 167,77 168,77 162,78 163,78 164,78 165,78 166,78 167,78 168,78 162,79 163,79 164,79 165,79 166,79 167,79 168,79 169,79 170,79 171,79 173,79 174,79 175,79 162,80 163,80 164,80 165,80 166,80 167,80 168,80 169,80 170,80 171,80 172,80 173,80 174,80 175,80 162,81 163,81 164,81 165,81 166,81 167,81 168,81 169,81 170,81 171,81 172,81 173,81 174,81 175,81 162,82 163,82 164,82 165,82 166,82 167,82 168,82 169,82 170,82 171,82 172,82 173,82 174,82 175,82 162,83 163,83 164,83 165,83 166,83 167,83 168,83 169,83 170,83 171,83 172,83 173,83 174,83 175,83 162,84 163,84 164,84 165,84 166,84 167,84 168,84 169,84 170,84 171,84 172,84 173,84 174,84 175,84 162,85 163,85 164,85 165,85 166,85 167,85 168,85 169,85 170,85 171,85 172,85 173,85 174,85 175,85 162,86 163,86 164,86 165,86 166,86 167,86 168,86 169,86 170,86 171,86 172,86 173,86 174,86 175,86
I_HALL_P: C2.2 C177.2 C178.2 C179.2 C180.2 U25.2
  other v1: 213,46 214,46 213,47 214,47 213,48 214,48 213,49 214,49 213,50 214,50 213,51 214,51 213,52 214,52 213,53 214,53 213,54 214,54 213,55 214,55 213,56 214,56 213,57 214,57 213,58 214,58 213,59 214,59 213,60 214,60 213,61 214,61 213,62 214,62 213,63 214,63 213,64 214,64 213,65 214,65 213,66 214,66 213,67 214,67 213,68 214,68 213,69 214,69 213,70 214,70 213,71 214,71 213,72 214,72 213,73 214,73 213,74 214,74 213,75 214,75 213,76 214,76 213,77 214,77 213,78 214,78 178,79 179,79 180,79 182,79 183,79 213,79 214,79 178,80 179,80 180,80 181,80 182,80 183,80 213,80 214,80 178,81 179,81 180,81 181,81 182,81 183,81 213,81 214,81 178,82 179,82 180,82 181,82 182,82 183,82 213,82 214,82 178,83 179,83 180,83 181,83 182,83 183,83 213,83 214,83 178,84 179,84 180,84 181,84 182,84 183,84 213,84 214,84 178,85 179,85 180,85 181,85 182,85 183,85 213,85 214,85 178,86 179,86 180,86 181,86 182,86 183,86 213,86 214,86 178,87 179,87 180,87 181,87 182,87 183,87 213,87 214,87 178,88 179,88 180,88 181,88 182,88 183,88 213,88 214,88 178,89 179,89 180,89 181,89 182,89 183,89 213,89 214,89 178,90 179,90 180,90 181,90 182,90 183,90 213,90 214,90 178,91 179,91 180,91 181,91 182,91 183,91 213,91 214,91 178,92 179,92 180,92 181,92 182,92 183,92 213,92 214,92 178,93 179,93 180,93 181,93 182,93 183,93 213,93 214,93 178,94 179,94 180,94 181,94 182,94 183,94 213,94 214,94 178,95 179,95 180,95 181,95 182,95 183,95 213,95 214,95 178,96 179,96 180,96 181,96 182,96 183,96 213,96 214,96 178,97 179,97 180,97 181,97 182,97 183,97 213,97 214,97 178,98 179,98 180,98 181,98 182,98 183,98 213,98 214,98 213,99 214,99 213,100 214,100 213,101 214,101 213,102 214,102 213,103 214,103 213,104 214,104 213,105 214,105 213,106 214,106 213,107 214,107 213,108 214,108 213,109 214,109 213,110 214,110 213,111 214,111 213,112 214,112 213,113 214,113 213,114 214,114 213,115 214,115 213,116 214,116 213,117 214,117 213,118 214,118 213,119 214,119 213,120 214,120 213,121 214,121 213,122 214,122 213,123 214,123 213,124 214,124 213,125 214,125
I_SW_NEG: C111.2 C112.2 C115.2 C117.2 C118.1 C120.2 R43.4 R184.1 U12.4 U13.12 U13.13 U13.14 U13.15 U13.16 | length 19.7
  Bottom Layer w0.25: v1(152,70) 152,69.905 151.816,69.722 151.816,69.143 C112.2@151.466,68.793 154.754,68.793 C115.2@154.8,68.747 154.8,69.706 155,69.905 v1(155,70) ; v1(153,70) 153,69.905 153.122,69.783 C111.2@153.122,68.767 ; U12.4@157.37,64.4 158,64.4 158.4,64.4 v1(159,65) 159,65.895 158,66.895 C117.2@158,67 158,68.434 R184.1@158.275,68.709 158,68.984 158,72.12 158.88,73 158.88,73.688 159.2,74.008 R43.4@159.49,74.008
  other v1: 147,66 148,66 147,67 148,67 147,68 148,68
I_SW_POS: R43.3 R182.1 | length 4
  Bottom Layer w0.25: R43.3@151.24,74.008 152.015,74.008 152.335,73.688 152.335,72.03 153.089,71.276 R182.1@153.114,71.276
ID1: R47.1 R55.2 R129.2 | length 5.3
  Top Layer w0.254: R129.2@66.829,19.774 66.829,20.735 67,20.906 v1(67,21)
  Bottom Layer w0.25: v1(67,21) 67.854,21 67.854,21.56 R47.1@68,21.707 R55.2@68,19.307
ID2: R46.1 R54.2 R131.2 | length 4.6
  Top Layer w0.254: v1(65.025,21) 65.025,20.944 65.294,20.675 R131.2@65.294,19.774
  Bottom Layer w0.254: v1(65.025,21) 65.898,21 ; R54.2@65.898,19.307 65.898,21 ; R46.1@65.898,21.707 65.898,21
ID3: R45.1 R53.2 R133.2 | length 4.9
  Top Layer w0.254: v1(63,21) 63.466,20.534 R133.2@63.466,19.776
  Bottom Layer w0.254: v1(63,21) 64.066,21 ; R53.2@64.066,19.307 64.066,21 ; R45.1@64.066,21.677 64.066,21
LED_GREEN: R48.2 R125.2 | length 8.3
  Top Layer w0.254: R125.2@69.656,19.77 69.656,22.067 v1(72.589,25)
  Bottom Layer w0.254: R48.2@72.427,23.247 72.427,24.744 72.589,24.906 v1(72.589,25)
LED_RED: R49.2 R127.2 | length 7.8
  Top Layer w0.254: R127.2@68.201,19.755 68.201,23.152 v1(70.049,25)
  Bottom Layer w0.254: v1(70.049,25) 70.049,23.268 R49.2@70.111,23.206
NetC1_1: C1.1 C173.1 C174.1 C175.1 C176.1 J6.1 TP16.1
  other v1: 197,169 198,169 197,170 198,170 197,171 198,171 197,172 198,172 197,173 198,173 197,174 198,174 197,175 198,175 197,176 198,176 197,177 198,177 197,178 198,178 197,179 198,179 197,180 198,180 197,181 198,181 197,182 198,182 197,183 198,183 197,184 198,184 197,185 198,185 197,186 198,186 197,187 198,187 197,188 198,188 197,189 198,189 197,190 198,190 197,191 198,191 197,192 198,192 197,193 198,193 197,194 198,194 197,195 198,195 197,196 198,196 197,197 198,197 197,198 198,198 197,199 198,199 197,200 198,200 197,201 198,201 197,202 198,202 197,203 198,203 197,204 198,204 197,205 198,205 197,206 198,206 197,207 198,207 197,208 198,208 197,209 198,209 197,210 198,210 197,211 198,211 197,212 198,212 197,213 198,213 197,214 198,214 197,215 198,215 197,216 198,216 197,217 198,217 197,218 198,218 197,219 198,219 197,220 198,220 197,221 198,221 197,222 198,222 197,223 198,223 197,224 198,224 197,225 198,225 197,226 198,226 197,227 198,227 197,228 198,228 197,229 198,229 197,230 198,230 197,231 198,231 197,232 198,232 197,233 198,233 197,234 198,234 197,235 198,235 197,236 198,236 197,237 198,237 197,238 198,238 197,239 198,239 197,240 198,240 197,241 198,241 197,242 198,242 197,243 198,243 197,244 198,244 197,245 198,245 197,246 198,246 197,247 198,247 197,248 198,248 197,249 198,249 197,250 198,250 197,251 198,251 197,252 198,252 197,253 198,253 197,254 198,254 197,255 198,255 197,256 198,256 197,257 198,257 197,258 198,258 197,259 198,259 197,260 198,260 197,261 198,261 197,262 198,262 197,263 198,263 197,264 198,264
NetC1_2: C1.2 C173.2 C174.2 C175.2 C176.2 D16.1 MD2.AC2 TP13.1 | length 4.6
  Bottom Layer w1: MD2.AC2@121.5,115.3 121.638,115.162 125.804,115.162 D16.1@125.943,115.023
  other v1: 144,118 145,118 146,118 147,118 148,118 149,118 150,118 151,118 152,118 153,118 154,118 155,118 156,118 157,118 158,118 159,118 144,119 145,119 146,119 147,119 148,119 149,119 150,119 151,119 152,119 153,119 154,119 155,119 156,119 157,119 158,119 159,119 144,120 145,120 146,120 147,120 148,120 149,120 150,120 151,120 152,120 153,120 154,120 155,120 156,120 157,120 158,120 159,120 144,121 145,121 146,121 147,121 148,121 149,121 150,121 151,121 152,121 153,121 154,121 155,121 156,121 157,121 158,121 159,121 144,122 145,122 146,122 147,122 148,122 149,122 150,122 151,122 152,122 153,122 154,122 155,122 156,122 157,122 158,122 159,122 144,123 145,123 146,123 147,123 148,123 149,123 150,123 151,123 152,123 153,123 154,123 155,123 156,123 157,123 158,123 159,123 166,170 167,170 166,171 167,171 166,172 167,172 166,173 167,173 166,174 167,174 166,175 167,175 166,176 167,176 166,177 167,177 166,178 167,178 166,179 167,179 166,180 167,180 166,181 167,181 166,182 167,182 166,183 167,183 166,184 167,184 166,185 167,185 166,186 167,186 166,187 167,187 166,188 167,188 166,189 167,189 166,190 167,190 166,191 167,191 166,192 167,192 166,193 167,193 166,194 167,194 166,195 167,195 166,196 167,196 166,197 167,197 166,198 167,198 166,199 167,199 166,200 167,200 166,201 167,201 166,202 167,202 166,203 167,203 166,204 167,204 166,205 167,205 166,206 167,206 166,207 167,207 166,208 167,208 166,209 167,209 166,210 167,210 166,211 167,211 166,212 167,212 166,213 167,213 166,214 167,214 166,215 167,215 166,216 167,216 166,217 167,217 166,218 167,218 166,219 167,219 166,220 167,220 166,221 167,221 166,222 167,222 166,223 167,223 166,224 167,224 166,225 167,225 166,226 167,226 166,227 167,227 166,228 167,228 166,229 167,229 166,230 167,230 166,231 167,231 166,232 167,232 166,233 167,233 166,234 167,234 166,235 167,235 166,236 167,236 166,237 167,237 166,238 167,238 166,239 167,239 166,240 167,240 166,241 167,241 166,242 167,242 166,243 167,243 166,244 167,244 166,245 167,245 166,246 167,246 166,247 167,247 166,248 167,248 166,249 167,249 166,250 167,250 166,251 167,251 166,252 167,252 166,253 167,253 166,254 167,254 166,255 167,255 166,256 167,256 166,257 167,257 166,258 167,258 166,259 167,259 166,260 167,260 166,261 167,261 166,262 167,262 166,263 167,263 166,264 167,264 166,265 167,265 166,266 167,266 166,267 167,267 166,268 167,268 166,269 167,269
NetC2_1: C2.1 C177.1 C178.1 C179.1 C180.1 J12.1 TP20.1
  other v1: 245,45 246,45 245,46 246,46 245,47 246,47 245,48 246,48 245,49 246,49 245,50 246,50 245,51 246,51 245,52 246,52 245,53 246,53 245,54 246,54 245,55 246,55 245,56 246,56 245,57 246,57 245,58 246,58 245,59 246,59 245,60 246,60 245,61 246,61 245,62 246,62 244,87 245,87 244,88 245,88 244,89 245,89 244,90 245,90 244,91 245,91 244,92 245,92 244,93 245,93 244,94 245,94 244,95 245,95 244,96 245,96 244,97 245,97 244,98 245,98 244,99 245,99 244,100 245,100 244,101 245,101 244,102 245,102 244,103 245,103 244,104 245,104 244,105 245,105 244,106 245,106 244,107 245,107 244,108 245,108 244,109 245,109 244,110 245,110 244,111 245,111 244,112 245,112 244,113 245,113 244,114 245,114 244,115 245,115 244,116 245,116 244,117 245,117 244,118 245,118 244,119 245,119 244,120 245,120 244,121 245,121 244,122 245,122 244,123 245,123 244,124 245,124 244,125 245,125 244,126 245,126
NetC7_1: C7.1 C8.1 C9.1 C19.2 C20.2 C21.2 R16.2 R22.1 R200.2 R201.2 R206.2 R207.2 R211.2 R212.2 R213.2 R214.2 | length 12.6
  Bottom Layer w1: C20.2@106.35,216.5 106.471,216.379 106.471,211.891 R22.1@106.592,211.77 ; C8.1@106.35,223.25 106.35,230.75 106.5,230.9 R16.2@106.592,230.9
  other v1: 8,213 9,213 10,213 11,213 12,213 13,213 8,214 9,214 10,214 11,214 12,214 13,214
NetC11_1: C11.1 C194.2
NetC12_1: C12.1 C197.2
NetC13_1: C13.1 C196.2
NetC22_1: C22.1 C64.1 J23.2 U4.1 U4.3 | length 23.3
  Top Layer w0.25: v1(42,30) 42,32 v1(45,35)
  Bottom Layer w0.25: C64.1@41,31.588 C64.1@40.781,31.806 40.826,31.851 C22.1@42.781,31.851 ; v1(42,30) 45.156,30 45.302,29.854 45.302,21.493 J23.2@45.27,21.461 ; C22.1@42.881,31.951 44.526,31.951 U4.1@44.625,32.05 ; U4.3@44.625,33.95 44.625,34.625 v1(45,35)
NetC23_1: C23.1 C193.2
NetC24_1: C24.1 C199.2
NetC25_1: C25.1 C192.2
NetC27_1: C27.1 J17.9 R44.2 | length 9.6
  Top Layer w0.254: R44.2@150.688,22.609 150.688,22.584 149.267,21.162 149.267,20.189 150.692,18.764 C27.1@150.692,18.739 150.867,18.564 J17.9@150.867,14.262
NetC29_1: C29.1 J17.15 R56.2 | length 9.8
  Top Layer w0.254: R56.2@147.588,22.609 147.588,22.584 146.22,21.215 146.216,21.215 146.216,20.14 147.592,18.764 C29.1@147.592,18.739 ; C29.1@147.592,18.714 148.467,17.839 J17.15@148.467,14.262
NetC30_1: C30.1 J17.68 R57.1 | length 7.9
  Top Layer w0.254: J17.68@124.467,10.862 124.467,7.684 v1(124.89,7.261) C30.1@124.89,5.583
  Bottom Layer w0.25: R57.1@124.825,9.725 124.825,7.326 v1(124.89,7.261)
NetC33_1: C33.1 J17.70 R68.1 | length 8.1
  Top Layer w0.254: C33.1@123.114,5.583 v1(123.114,7.196) 123.667,7.748 J17.70@123.667,10.862
  Bottom Layer w0.254: R68.1@122.862,9.725 123.114,9.473 v1(123.114,7.196)
NetC34_1: C34.1 J17.21 R77.2 | length 10.1
  Top Layer w0.254: R77.2@144.488,22.609 144.488,22.584 143.125,21.22 143.125,20.131 144.492,18.764 144.492,18.714 146.067,17.139 J17.21@146.067,14.262
NetC35_1: C35.1 J17.72 R78.1 | length 8.8
  Top Layer w0.254: C35.1@121.338,5.583 121.338,6.708 v1(121.92,7.289) 122.867,8.236 J17.72@122.867,10.862
  Bottom Layer w0.25: R78.1@120.899,9.725 120.899,8.31 v1(121.92,7.289)
NetC40_1: C40.1 J17.25 R85.2 | length 10.7
  Top Layer w0.254: R85.2@141.438,22.609 141.438,22.584 140.467,21.612 140.467,19.739 141.442,18.764 C40.1@141.442,18.739 ; C40.1@141.442,18.714 141.79,18.366 142.399,18.366 144.344,16.421 144.344,14.385 J17.25@144.467,14.262
NetC41_1: C41.1 J17.74 R86.1 | length 9.7
  Top Layer w0.254: C41.1@119.562,5.583 119.848,5.868 119.848,6.304 v1(120.602,7.058) 121.944,8.4 121.944,10.739 J17.74@122.067,10.862
  Bottom Layer w0.25: R86.1@118.936,9.725 118.936,8.725 v1(120.602,7.058)
NetC43_1: C43.1 J17.76 R94.1 R149.1 | length 12.6
  Top Layer w0.254: C43.1@117.787,5.583 118.027,5.824 118.027,6.851 118.176,7 v1(118.859,7) 119.542,7 121.144,8.602 121.144,10.739 J17.76@121.267,10.862
  Bottom Layer w0.25: R94.1@116.973,9.725 116.973,8.886 v1(118.859,7) 118.377,6.518 118.377,6.133 R149.1@118.027,5.783
NetC45_2: C45.2 R104.2 U2.14 | length 4.3
  Bottom Layer w0.25: R104.2@86.275,28 86.275,29.9 C45.2@86.175,30 86.175,32.02 U2.14@86.325,32.171
NetC46_1: C46.1 J17.78 R109.1 R150.1 | length 13.5
  Top Layer w0.254: C46.1@116.011,5.583 116.3,5.872 116.3,6.3 v1(117.15,7.15) 118,8 119.9,8 120.412,8.512 120.412,10.807 J17.78@120.467,10.862
  Bottom Layer w0.25: R109.1@115.01,9.725 115.01,9.7 117.15,7.56 v1(117.15,7.15) 117.083,7.083 117.083,6.877 116.014,5.808 R150.1@116.014,5.783
NetC58_1: C58.1 U5.4 | length 2.6
  Bottom Layer w0.25: C58.1@30.65,25.887 30.65,25.912 31.325,26.587 U5.4@32.91,26.587
NetC58_2: C58.2 L7.1 U5.2 | length 9.5
  Top Layer w0.25: v1(30,23) 30,24 33.087,27.087 v1(35.65,27.087)
  Bottom Layer w0.25: v1(30,23) 30,23.095 30.3,23.395 30.3,23.937 C58.2@30.65,24.287
NetC63_2: C63.2 R144.1 R146.2 U5.6 | length 6.4
  Bottom Layer w0.25: R146.2@27.271,29.26 30.623,29.26 C63.2@30.65,29.287 30.65,29.262 32.3,27.612 32.885,27.612 U5.6@32.91,27.587
NetC65_1: C65.1 C191.2
NetC70_1: C70.1 C72.1 C169.1 C170.1 C171.2 J22.2 R143.2 U5.1 | length 20.7
  Top Layer w0.25: v2(25,24) 25,31 27,33 v1(36,33)
  Bottom Layer w0.25: v2(25,24) 26.763,24 R143.2@26.85,24.087
NetC71_1: C71.1 C195.2
NetC77_1: C77.1 C80.2 R152.2 U6.3 | length 9.5
  Bottom Layer w0.25: U6.3@32.001,144.763 32.042,144.804 32.042,147.272 C77.1@32.083,147.313 32.083,148.083 34.14,150.14 34.14,150.823 R152.2@34.49,151.173 34.54,151.223 C80.2@36.507,151.223
NetC77_2: C77.2 C79.2 R151.2 U6.2 | length 9.5
  Bottom Layer w0.25: C79.2@29.721,151.223 32.123,151.223 R151.2@32.173,151.173 32.173,150.173 31,149 31,147.43 C77.2@30.883,147.313 30.807,147.237 30.807,144.839 U6.2@30.731,144.763
NetC81_1: C81.1 R154.1 | length 1.8
  Bottom Layer w0.25: C81.1@43.441,125.125 45.161,125.125 R154.1@45.236,125.2
NetC86_2: C86.2 R162.2 R164.2 U7.2 | length 46.5
  Bottom Layer w0.25: U7.2@47.266,144.913 47.208,144.971 47.208,147.142 47.15,147.2 47.15,149.05 47.2,149.1 47.2,150.2 50,153 50,184 51,185 51,188.3 R162.2@51.5,188.8
  Bottom Layer w0.254: R162.2@51,189 51.498,189 R162.2@51.599,188.899 ; R162.2@51.5,188.8 R162.2@51.599,188.8
NetC111_1: C111.1 C112.1 R181.2 U12.1 | length 6.5
  Bottom Layer w0.25: R181.2@149.709,67.221 149.744,67.257 C111.1@153.122,67.257 153.227,67.257 153.497,66.987 153.497,66.882 153.56,66.819 U12.1@153.56,64.4
NetC115_1: C115.1 R182.2 U12.2 | length 7.6
  Bottom Layer w0.25: R182.2@154.714,71.276 154.739,71.276 155.625,70.39 155.625,67.997 154.83,67.201 U12.2@154.83,64.4
NetC117_1: C117.1 R184.2 U12.3 | length 4.6
  Bottom Layer w0.25: U12.3@156.1,64.4 156.1,65.6 156.5,66 156.5,66.99 C117.1@156.49,67 156.49,68.524 R184.2@156.675,68.709
NetC125_1: C125.1 R186.2 U14.4 | length 4.5
  Bottom Layer w0.25: R186.2@16,20 15.839,20.161 C125.1@15.839,22.357 15.839,24.044 U14.4@16.095,24.3
NetC128_1: C128.1 R189.2 U15.4 | length 5.6
  Bottom Layer w0.25: R189.2@142.242,39.957 142.387,39.812 145.318,39.812 145.588,39.542 145.588,39.435 146.118,38.905 U15.4@147.3,38.905
NetC134_1: C134.1 R193.2 R194.1 | length 4.6
  Bottom Layer w0.25: R194.1@228,17 228,16.975 228.975,16 C134.1@230.2,16 R193.2@230.2,18
NetC135_2: C135.2 L1.2 TP5.1 U20.3 | length 11.5
  Bottom Layer w0.25: TP5.1@234.768,18.007 234.775,18 235,18 237.021,15.979 238.138,15.979 L1.2@238.42,15.697 238.724,16 C135.2@240.349,16 240.399,15.95 U20.3@240.399,11.226
NetC136_1: C136.1 R196.2 R197.1 | length 4.9
  Bottom Layer w0.25: R197.1@200,17.6 200,17.575 201.225,16.35 201.85,16.35 R196.2@202.2,16 C136.1@202.2,18
NetC138_2: C138.2 L2.2 TP8.1 U22.3 | length 10.9
  Bottom Layer w0.25: TP8.1@211,18 214.357,18 L2.2@214.577,17.78 214.55,17.78 214.175,17.405 C138.2@214.175,16 214.175,12.421 U22.3@212.98,11.226
NetC139_1: C139.1 R208.2 R209.1 | length 4.5
  Bottom Layer w0.25: R209.1@173,16.8 173,16.775 173.35,16.425 173.375,16.425 173.8,16 R208.2@175.2,16 C139.1@175.2,18
NetC140_2: C140.2 L3.2 TP11.1 U24.3 | length 11.4
  Bottom Layer w0.25: TP11.1@182.294,18.102 182.298,18.097 182.637,18.097 182.734,18 183,18 L3.2@185.75,18 ; U24.3@185.561,11.226 185.561,11.551 186.175,12.164 C140.2@186.175,16 186.175,17.575 L3.2@186,17.75 ; L3.2@185.75,18 L3.2@186,17.75 ; L3.2@185.75,18 L3.2@186,17.75 ; L3.2@185.75,18 L3.2@186,17.75
NetC153_1: C153.1 J17.58 R69.1 | length 7.6
  Top Layer w0.254: J17.58@128.244,9.725 128.244,9.341 v1(129.941,7.643) 131.638,5.946 R69.1@131.764,5.946
  Bottom Layer w0.25: v1(129.941,7.643) 130.467,8.169 130.467,9.721 C153.1@130.463,9.725
NetC154_1: C154.1 J17.60 R71.1 | length 8.2
  Top Layer w0.254: J17.60@127.667,10.862 127.79,10.739 127.79,8.702 129.988,6.505 R71.1@129.988,5.946
  Bottom Layer w0.25: C154.1@128.5,9.725 128.5,8.087 128.889,7.698 v1(128.889,7.604)
NetC155_1: C155.1 J17.64 R74.1 | length 7.4
  Top Layer w0.254: J17.64@126.067,10.862 126.067,7.75 126.436,7.381 R74.1@126.436,5.946
  Bottom Layer w0.25: v1(126.251,7.566) 126.251,7.661 126.569,7.978 C155.1@126.569,9.725
NetC162_1: C162.1 R202.2 R203.1 U25.8 | length 7.8
  Bottom Layer w0.25: U25.8@174.595,67.247 174.595,65.405 175.425,64.575 175.425,64.35 175.775,64 C162.1@175.8,64 R203.1@175.8,62 R202.2@175.8,60
NetC163_1: C163.1 C190.2
NetC164_1: C164.1 C198.2
NetC172_1: C172.1 R143.1 R145.1 U5.5 | length 8.9
  Bottom Layer w0.25: R145.1@28.45,22.087 R143.1@28.45,24.087 C172.1@28.45,26.087 29.415,26.087 30.415,27.087 U5.5@32.91,27.087
NetD3_2: D3.2 D7.1 | length 4.1
  Bottom Layer w1: D7.1@77,73.977 D3.2@81.057,73.977
NetD4_2: D4.2 D8.1 | length 4.5
  Bottom Layer w1: D8.1@76.7,114.323 77.2,114.823 78.28,114.823 78.457,115 D4.2@80.957,115
NetD7_2: D7.2 D11.1 | length 3.9
  Bottom Layer w1: D7.2@77,77.977 D11.1@77,81.84
NetD8_2: D8.2 D12.1 | length 3.5
  Bottom Layer w1: D12.1@76.7,106.786 D8.2@76.7,110.323
NetD15_1: D15.1 MD2.AC1 R43.1 TP15.1 | length 4.7
  Bottom Layer w1: MD2.AC1@121.5,73.7 121.65,73.85 125.893,73.85 D15.1@126.043,74
  other v1: 141,73 142,73 143,73 144,73 141,74 142,74 143,74 144,74 145,74 146,74 147,74 148,74 141,75 142,75 143,75 144,75 145,75 146,75 147,75 148,75 141,76 142,76 143,76 144,76 145,76 146,76 147,76 148,76 149,76 142,77 143,77 144,77 145,77 146,77 147,77 148,77 149,77 143,78 144,78 145,78 146,78 147,78 148,78 149,78 144,79 145,79 146,79 147,79 148,79 149,79 144,80 145,80 146,80 147,80 148,80 149,80 144,81 145,81 146,81 147,81 148,81 149,81 144,82 145,82 146,82 147,82 148,82 149,82 144,83 145,83 146,83 147,83 148,83 149,83 144,84 145,84 146,84 147,84 148,84 149,84 144,85 145,85 146,85 147,85 148,85 149,85 144,86 145,86 146,86 147,86 148,86 149,86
